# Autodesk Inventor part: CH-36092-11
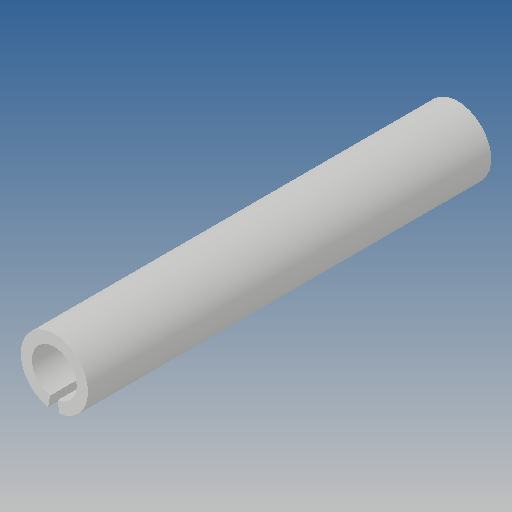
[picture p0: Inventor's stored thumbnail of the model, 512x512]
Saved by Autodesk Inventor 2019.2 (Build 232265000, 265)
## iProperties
Created: 2012-09
Part Number: CH-36092-11
Material: Ogólny
Document SubType Name: Modeling
Designer: CADENGINEERING4
Density: 1 g/cm^3
Appearance: Domyślna
Author: CADENGINEERING4
Revision Number: ÈÎºÎ
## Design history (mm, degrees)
feature "À­Éì1"
node "Bryła1"
